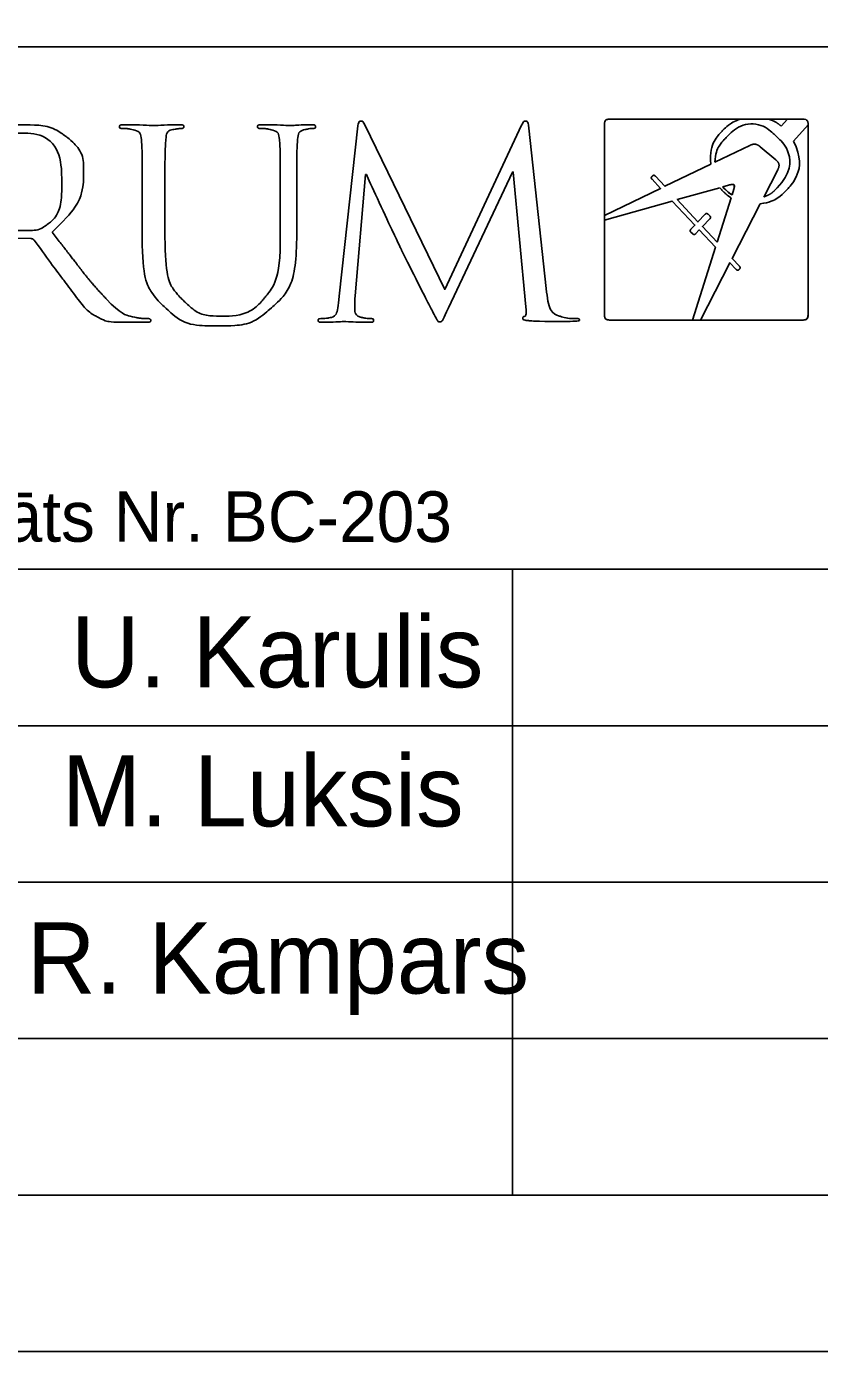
# Model space of a CAD drawing. Extents: x 321079 to 321220, y 257030 to 257220.
# Drawn here: x 321163.79 to 321176.96, y 257029.87 to 257051.88 of the extents above; entities that cross this region are included whole.
import ezdxf

# ---------------------------------------------------------------- set-up
doc = ezdxf.new("R2010")
doc.units = 0
doc.layers.add('RAMI_PLAN_####_TKST_#', color=7, linetype='Continuous')

msp = doc.modelspace()

# ---------------------------------------------------------------- linework, layer by layer
at = {"layer": 'RAMI_PLAN_####_TKST_#'}
for p, q in [((321169.297, 257050.226), (321168.985, 257047.395)), ((321172.424, 257047.521), (321172.133, 257050.187)), ((321165.715, 257048.984), (321165.715, 257048.351)), ((321166.093, 257048.376), (321166.093, 257048.984)), ((321168.008, 257048.984), (321168.008, 257048.442)), ((321168.281, 257048.52), (321168.281, 257048.984)), ((321163.331, 257048.359), (321163.865, 257048.351)), ((321165.446, 257046.961), (321165.754, 257046.961)), ((321218.314, 257042.859), (321152.318, 257042.859)), ((321171.864, 257042.859), (321171.864, 257032.464)), ((321191.073, 257040.261), (321152.318, 257040.261)), ((321191.073, 257037.662), (321152.318, 257037.662)), ((321210.803, 257035.063), (321152.318, 257035.063)), ((321191.073, 257032.464), (321152.318, 257032.464))]:
    msp.add_line(p, q, dxfattribs=at)
for points in [[(321079.019, 257029.866), (321079.019, 257219.866), (321218.314, 257219.866), (321218.314, 257029.866)], [(321152.318, 257051.537), (321218.314, 257051.537), (321218.314, 257029.866), (321152.318, 257029.866)]]:
    msp.add_lwpolyline(points, close=True, dxfattribs=at)
for points in [[(321172.015, 257050.235), (321170.739, 257047.508), (321169.41, 257050.239)], [(321173.39, 257050.236), (321173.39, 257048.738), (321174.321, 257049.186), (321174.181, 257049.337)], [(321175.649, 257050.336), (321173.49, 257050.336)], [(321176.432, 257050.336), (321176.113, 257050.336)], [(321176.325, 257050.222), (321176.432, 257050.336)], [(321176.773, 257047.099), (321176.773, 257050.236), (321176.773, 257050.243), (321176.531, 257049.968)], [(321175.224, 257049.621), (321175.802, 257049.899)], [(321175.978, 257049.877), (321176.236, 257049.659)], [(321174.236, 257049.389), (321174.393, 257049.221), (321175.154, 257049.587)], [(321176.268, 257049.496), (321176.035, 257049.042)], [(321169.249, 257047.4), (321169.423, 257049.414), (321169.441, 257049.414)], [(321170.8, 257047.2), (321171.863, 257049.457), (321171.876, 257049.457), (321172.085, 257047.218)], [(321174.182, 257049.386), (321174.187, 257049.391)], [(321175.306, 257049.197), (321174.599, 257048.999), (321174.943, 257048.63), (321175.062, 257048.755)], [(321175.47, 257049.243), (321175.356, 257049.211)], [(321175.509, 257049.08), (321175.539, 257049.174)], [(321174.826, 257048.507), (321174.891, 257048.575), (321174.517, 257048.976), (321173.39, 257048.66)], [(321175.26, 257048.29), (321175.493, 257049.03)], [(321175.976, 257048.929), (321175.51, 257048.022), (321175.631, 257047.892)], [(321173.39, 257048.66), (321173.39, 257047.099)], [(321175.141, 257048.68), (321175.017, 257048.551), (321175.26, 257048.29)], [(321175.111, 257048.756), (321175.14, 257048.729)], [(321173.49, 257046.999), (321174.852, 257046.999), (321175.234, 257048.207), (321174.965, 257048.496), (321174.904, 257048.432)], [(321174.855, 257048.431), (321174.827, 257048.458)], [(321175.576, 257047.84), (321175.473, 257047.95), (321174.984, 257046.999)], [(321175.629, 257047.843), (321175.625, 257047.839)], [(321174.984, 257046.999), (321176.673, 257046.999)]]:
    msp.add_lwpolyline(points, dxfattribs=at)
for points, degree in [([(321164.217, 257048.459), (321164.608, 257048.819), (321164.742, 257049.141), (321164.742, 257049.462), (321164.742, 257049.462), (321164.742, 257049.761), (321164.551, 257049.974), (321164.443, 257050.052), (321164.443, 257050.052), (321164.213, 257050.217), (321163.922, 257050.243), (321163.648, 257050.243), (321163.648, 257050.243), (321163.514, 257050.243), (321163.184, 257050.23), (321163.136, 257050.23), (321163.136, 257050.23), (321163.114, 257050.23), (321162.841, 257050.243), (321162.645, 257050.243), (321162.645, 257050.243), (321162.597, 257050.243), (321162.576, 257050.235), (321162.576, 257050.209), (321162.576, 257050.209), (321162.576, 257050.191), (321162.593, 257050.183), (321162.61, 257050.183), (321162.61, 257050.183), (321162.65, 257050.183), (321162.723, 257050.178), (321162.758, 257050.169), (321162.758, 257050.169), (321162.901, 257050.139), (321162.936, 257050.07), (321162.945, 257049.922), (321162.945, 257049.922), (321162.954, 257049.783), (321162.954, 257049.662), (321162.954, 257048.984)], 3), ([(321166.093, 257048.984), (321166.093, 257049.662), (321166.093, 257049.783), (321166.102, 257049.922), (321166.102, 257049.922), (321166.11, 257050.074), (321166.145, 257050.152), (321166.262, 257050.169), (321166.262, 257050.169), (321166.314, 257050.178), (321166.34, 257050.183), (321166.371, 257050.183), (321166.371, 257050.183), (321166.388, 257050.183), (321166.405, 257050.191), (321166.405, 257050.209), (321166.405, 257050.209), (321166.405, 257050.235), (321166.384, 257050.243), (321166.336, 257050.243), (321166.336, 257050.243), (321166.206, 257050.243), (321165.945, 257050.23), (321165.906, 257050.23), (321165.906, 257050.23), (321165.867, 257050.23), (321165.602, 257050.243), (321165.407, 257050.243), (321165.407, 257050.243), (321165.359, 257050.243), (321165.337, 257050.235), (321165.337, 257050.209), (321165.337, 257050.209), (321165.337, 257050.191), (321165.355, 257050.183), (321165.372, 257050.183), (321165.372, 257050.183), (321165.411, 257050.183), (321165.485, 257050.178), (321165.52, 257050.169), (321165.52, 257050.169), (321165.663, 257050.139), (321165.698, 257050.07), (321165.707, 257049.922), (321165.707, 257049.922), (321165.715, 257049.783), (321165.715, 257049.662), (321165.715, 257048.984)], 3), ([(321168.524, 257050.243), (321168.394, 257050.243), (321168.19, 257050.23), (321168.16, 257050.23), (321168.16, 257050.23), (321168.134, 257050.23), (321167.895, 257050.243), (321167.699, 257050.243), (321167.699, 257050.243), (321167.652, 257050.243), (321167.63, 257050.235), (321167.63, 257050.209), (321167.63, 257050.209), (321167.63, 257050.191), (321167.647, 257050.183), (321167.665, 257050.183), (321167.665, 257050.183), (321167.704, 257050.183), (321167.778, 257050.178), (321167.813, 257050.169), (321167.813, 257050.169), (321167.956, 257050.139), (321167.99, 257050.07), (321167.999, 257049.922), (321167.999, 257049.922), (321168.008, 257049.783), (321168.008, 257049.662), (321168.008, 257048.984)], 3), ([(321168.281, 257048.984), (321168.281, 257049.662), (321168.281, 257049.783), (321168.29, 257049.922), (321168.29, 257049.922), (321168.299, 257050.074), (321168.333, 257050.148), (321168.451, 257050.169), (321168.451, 257050.169), (321168.503, 257050.183), (321168.529, 257050.183), (321168.559, 257050.183), (321168.559, 257050.183), (321168.577, 257050.183), (321168.594, 257050.191), (321168.594, 257050.209), (321168.594, 257050.209), (321168.594, 257050.235), (321168.572, 257050.243), (321168.524, 257050.243)], 3), ([(321169.41, 257050.239), (321169.388, 257050.287), (321169.371, 257050.304), (321169.345, 257050.304), (321169.345, 257050.304), (321169.319, 257050.304), (321169.306, 257050.274), (321169.297, 257050.226)], 3), ([(321172.133, 257050.187), (321172.124, 257050.269), (321172.111, 257050.304), (321172.081, 257050.304), (321172.081, 257050.304), (321172.05, 257050.304), (321172.033, 257050.274), (321172.015, 257050.235)], 3), ([(321176.773, 257047.099), (321176.773, 257047.038), (321176.736, 257046.999), (321176.673, 257046.999), (321176.673, 257046.999), (321176.673, 257046.999), (321173.49, 257046.999), (321173.49, 257046.999), (321173.49, 257046.999), (321173.425, 257046.999), (321173.39, 257047.038), (321173.39, 257047.099), (321173.39, 257047.099), (321173.39, 257047.099), (321173.39, 257050.236), (321173.39, 257050.236), (321173.39, 257050.236), (321173.39, 257050.298), (321173.428, 257050.336), (321173.49, 257050.336), (321173.49, 257050.336), (321173.49, 257050.336), (321176.673, 257050.336), (321176.673, 257050.336), (321176.673, 257050.336), (321176.737, 257050.336), (321176.773, 257050.291), (321176.773, 257050.236), (321176.773, 257050.236), (321176.773, 257050.236), (321176.773, 257047.099), (321176.773, 257047.099)], 3), ([(321173.49, 257050.336), (321173.428, 257050.336), (321173.39, 257050.298), (321173.39, 257050.236)], 2), ([(321175.154, 257049.587), (321175.138, 257049.786), (321175.204, 257049.991), (321175.353, 257050.147), (321175.353, 257050.147), (321175.438, 257050.236), (321175.54, 257050.299), (321175.649, 257050.336)], 3), ([(321176.257, 257049.193), (321176.49, 257049.438), (321176.486, 257049.82), (321176.248, 257050.047), (321176.248, 257050.047), (321176.01, 257050.273), (321175.628, 257050.259), (321175.395, 257050.014), (321175.395, 257050.014), (321175.289, 257049.902), (321175.232, 257049.762), (321175.224, 257049.621)], 3), ([(321176.113, 257050.336), (321176.188, 257050.311), (321176.26, 257050.273), (321176.325, 257050.222)], 2), ([(321163.301, 257050.026), (321163.301, 257050.052), (321163.314, 257050.07), (321163.336, 257050.078), (321163.336, 257050.078), (321163.379, 257050.091), (321163.496, 257050.105), (321163.626, 257050.105), (321163.626, 257050.105), (321164.091, 257050.105), (321164.378, 257049.779), (321164.378, 257049.236), (321164.378, 257049.236), (321164.378, 257048.906), (321164.265, 257048.672), (321164.113, 257048.568), (321164.113, 257048.568), (321164.013, 257048.498), (321163.891, 257048.485), (321163.787, 257048.485), (321163.787, 257048.485), (321163.596, 257048.485), (321163.396, 257048.515), (321163.331, 257048.555), (321163.331, 257048.555), (321163.31, 257048.568), (321163.301, 257048.585), (321163.301, 257048.607)], 3), ([(321176.531, 257049.968), (321176.66, 257049.704), (321176.618, 257049.375), (321176.403, 257049.148), (321176.403, 257049.148), (321176.285, 257049.024), (321176.133, 257048.951), (321175.976, 257048.929)], 3), ([(321175.802, 257049.899), (321175.854, 257049.925), (321175.934, 257049.915), (321175.978, 257049.877)], 2), ([(321176.236, 257049.659), (321176.28, 257049.621), (321176.295, 257049.548), (321176.268, 257049.496)], 2), ([(321169.441, 257049.414), (321169.488, 257049.297), (321169.975, 257048.255), (321170.014, 257048.177), (321170.014, 257048.177), (321170.035, 257048.133), (321170.409, 257047.382), (321170.522, 257047.17), (321170.522, 257047.17), (321170.604, 257047.013), (321170.626, 257046.97), (321170.656, 257046.97), (321170.656, 257046.97), (321170.695, 257046.97), (321170.708, 257047.009), (321170.8, 257047.2)], 3), ([(321174.181, 257049.337), (321174.168, 257049.351), (321174.168, 257049.373), (321174.182, 257049.386)], 2), ([(321174.187, 257049.391), (321174.201, 257049.404), (321174.223, 257049.403), (321174.236, 257049.389)], 2), ([(321175.493, 257049.03), (321175.452, 257049.056), (321175.413, 257049.086), (321175.376, 257049.121), (321175.376, 257049.121), (321175.351, 257049.145), (321175.327, 257049.171), (321175.306, 257049.197)], 3), ([(321175.539, 257049.174), (321175.539, 257049.174), (321175.509, 257049.08), (321175.509, 257049.08), (321175.509, 257049.08), (321175.472, 257049.102), (321175.437, 257049.129), (321175.404, 257049.16), (321175.404, 257049.16), (321175.387, 257049.176), (321175.371, 257049.193), (321175.356, 257049.211), (321175.356, 257049.211), (321175.356, 257049.211), (321175.47, 257049.243), (321175.47, 257049.243), (321175.47, 257049.243), (321175.525, 257049.261), (321175.557, 257049.23), (321175.539, 257049.174)], 3), ([(321175.356, 257049.211), (321175.371, 257049.193), (321175.387, 257049.176), (321175.404, 257049.16), (321175.404, 257049.16), (321175.437, 257049.129), (321175.472, 257049.102), (321175.509, 257049.08)], 3), ([(321175.539, 257049.174), (321175.557, 257049.23), (321175.525, 257049.261), (321175.47, 257049.243)], 2), ([(321176.035, 257049.042), (321176.116, 257049.075), (321176.192, 257049.125), (321176.257, 257049.193)], 2), ([(321175.062, 257048.755), (321175.075, 257048.769), (321175.097, 257048.769), (321175.111, 257048.756)], 2), ([(321175.14, 257048.729), (321175.153, 257048.716), (321175.154, 257048.694), (321175.141, 257048.68)], 2), ([(321165.12, 257047.348), (321164.868, 257047.617), (321164.573, 257048.003), (321164.217, 257048.459)], 2), ([(321165.715, 257048.351), (321165.715, 257047.717), (321165.88, 257047.413), (321166.093, 257047.209), (321166.093, 257047.209), (321166.401, 257046.918), (321166.84, 257046.901), (321166.987, 257046.901), (321166.987, 257046.901), (321167.244, 257046.901), (321167.569, 257046.944), (321167.882, 257047.222), (321167.882, 257047.222), (321168.229, 257047.53), (321168.281, 257048.051), (321168.281, 257048.52)], 3), ([(321168.008, 257048.442), (321168.008, 257047.995), (321167.956, 257047.626), (321167.756, 257047.378), (321167.756, 257047.378), (321167.6, 257047.191), (321167.339, 257047.065), (321167.074, 257047.065), (321167.074, 257047.065), (321166.827, 257047.065), (321166.631, 257047.105), (321166.419, 257047.304), (321166.419, 257047.304), (321166.232, 257047.482), (321166.093, 257047.751), (321166.093, 257048.376)], 3), ([(321174.827, 257048.458), (321174.813, 257048.471), (321174.813, 257048.493), (321174.826, 257048.507)], 2), ([(321174.904, 257048.432), (321174.891, 257048.418), (321174.869, 257048.418), (321174.855, 257048.431)], 2), ([(321163.865, 257048.351), (321163.891, 257048.351), (321163.904, 257048.342), (321163.922, 257048.324)], 2), ([(321163.922, 257048.324), (321164.009, 257048.212), (321164.213, 257047.921), (321164.395, 257047.682), (321164.395, 257047.682), (321164.642, 257047.356), (321164.795, 257047.144), (321164.981, 257047.044), (321164.981, 257047.044), (321165.094, 257046.983), (321165.203, 257046.961), (321165.446, 257046.961)], 3), ([(321175.625, 257047.839), (321175.611, 257047.825), (321175.589, 257047.826), (321175.576, 257047.84)], 2), ([(321175.631, 257047.892), (321175.644, 257047.878), (321175.643, 257047.856), (321175.629, 257047.843)], 2), ([(321172.085, 257047.218), (321172.093, 257047.139), (321172.089, 257047.065), (321172.068, 257047.061), (321172.068, 257047.061), (321172.046, 257047.057), (321172.037, 257047.048), (321172.037, 257047.031), (321172.037, 257047.031), (321172.037, 257047.009), (321172.059, 257046.996), (321172.159, 257046.987), (321172.159, 257046.987), (321172.319, 257046.974), (321172.975, 257046.974), (321172.975, 257047), (321172.975, 257047), (321172.975, 257047.018), (321172.962, 257047.022), (321172.94, 257047.022), (321172.94, 257047.022), (321172.897, 257047.022), (321172.784, 257047.022), (321172.658, 257047.061), (321172.658, 257047.061), (321172.471, 257047.122), (321172.441, 257047.365), (321172.424, 257047.521)], 3), ([(321165.754, 257046.961), (321165.832, 257046.961), (321165.858, 257046.97), (321165.858, 257046.996), (321165.858, 257046.996), (321165.858, 257047.009), (321165.841, 257047.022), (321165.819, 257047.022), (321165.819, 257047.022), (321165.793, 257047.022), (321165.733, 257047.022), (321165.65, 257047.035), (321165.65, 257047.035), (321165.541, 257047.052), (321165.355, 257047.1), (321165.12, 257047.348)], 3), ([(321168.681, 257047.022), (321168.659, 257047.022), (321168.637, 257047.013), (321168.637, 257047), (321168.637, 257047), (321168.637, 257046.97), (321168.668, 257046.961), (321168.711, 257046.961), (321168.711, 257046.961), (321168.828, 257046.961), (321169.037, 257046.974), (321169.076, 257046.974), (321169.076, 257046.974), (321169.11, 257046.974), (321169.319, 257046.961), (321169.48, 257046.961), (321169.48, 257046.961), (321169.532, 257046.961), (321169.558, 257046.97), (321169.558, 257047), (321169.558, 257047), (321169.558, 257047.013), (321169.54, 257047.022), (321169.523, 257047.022), (321169.523, 257047.022), (321169.497, 257047.022), (321169.432, 257047.026), (321169.358, 257047.044), (321169.358, 257047.044), (321169.293, 257047.057), (321169.245, 257047.113), (321169.245, 257047.178), (321169.245, 257047.178), (321169.245, 257047.252), (321169.245, 257047.33), (321169.249, 257047.4)], 3), ([(321168.985, 257047.395), (321168.967, 257047.23), (321168.954, 257047.061), (321168.811, 257047.035), (321168.811, 257047.035), (321168.746, 257047.022), (321168.715, 257047.022), (321168.681, 257047.022)], 3), ([(321173.39, 257047.099), (321173.39, 257047.038), (321173.425, 257046.999), (321173.49, 257046.999)], 2), ([(321176.673, 257046.999), (321176.736, 257046.999), (321176.773, 257047.038), (321176.773, 257047.099)], 2)]:
    msp.add_open_spline(points, degree=degree, dxfattribs=at)

# ---------------------------------------------------------------- texts
msp.add_text('Māris Luksis, sertifikāts Nr. BC-203', height=0.84, rotation=359.9635, dxfattribs=at).set_placement((321153.319, 257043.324))
for s, p in [('U. Karulis', (321164.533, 257040.898)), ('M. Luksis', (321164.381, 257038.589)), ('R. Kampars', (321163.799, 257035.812))]:
    msp.add_text(s, height=1.1812, dxfattribs=at).set_placement(p)

doc.saveas('drawing.dxf')
